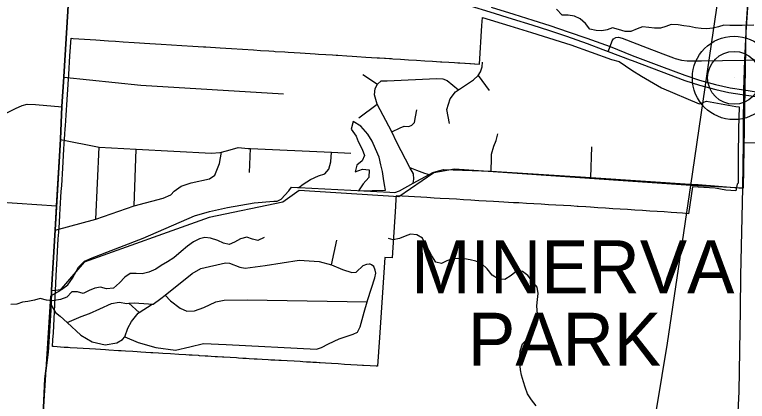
# Model space of a CAD drawing. Extents: x 0 to 34, y 0 to 22.
# Drawn here: x 26.126 to 27.434, y 4.179 to 4.869 of the extents above; entities that cross this region are included whole.
import ezdxf

# ---------------------------------------------------------------- set-up
doc = ezdxf.new("R2010")
doc.units = 0
for name, color, linetype in [('GM_X_City_Street', 7, 'Continuous'), ('GM_X_Corporation', 7, 'Continuous'), ('GM_X_Corporation_Text', 7, 'Continuous'), ('GM_X_County_Road', 7, 'Continuous'), ('GM_X_Minor_Lake', 7, 'Continuous'), ('GM_X_Minor_River', 7, 'Continuous'), ('GM_X_Rail_Line', 7, 'Continuous'), ('GM_X_State_Route', 7, 'Continuous'), ('GM_X_Unincorporated', 7, 'Continuous'), ('GM_X_Unincorporated_Location', 7, 'Continuous')]:
    doc.layers.add(name, color=color, linetype=linetype)

msp = doc.modelspace()

# ---------------------------------------------------------------- linework, layer by layer
at = {"layer": 'GM_X_City_Street'}
for p, q in [((26.7469, 4.7623), (26.7735, 4.745)), ((26.9529, 4.7602), (26.9729, 4.7335)), ((26.74, 4.6848), (26.7725, 4.7094)), ((26.2703, 4.5039), (26.2767, 4.6323)), ((27.1542, 4.5784), (27.1557, 4.6329)), ((26.3387, 4.528), (26.3427, 4.6289)), ((26.5447, 4.5871), (26.5467, 4.6302)), ((27.3456, 4.5656), (27.4257, 4.5596)), ((25.942, 4.5444), (26.2001, 4.5279)), ((26.6909, 4.4223), (26.7007, 4.4663)), ((26.3292, 4.3538), (26.3479, 4.3372))]:
    msp.add_line(p, q, dxfattribs=at)
for points in [[(26.9017, 4.6745), (26.8972, 4.6996), (26.9032, 4.7186), (26.9126, 4.7315), (26.9178, 4.7351), (26.9448, 4.7525), (26.9529, 4.7602), (26.957, 4.7669), (26.9601, 4.776), (26.9609, 4.7844)], [(26.2133, 4.7576), (26.3507, 4.7434), (26.6052, 4.7275)], [(26.7735, 4.745), (26.7796, 4.7507), (26.7903, 4.751), (26.8786, 4.7552), (26.8901, 4.7548), (26.8978, 4.7513), (26.9178, 4.7351)], [(26.8371, 4.5683), (26.838, 4.5753), (26.8377, 4.5852), (26.8309, 4.5963), (26.808, 4.6408), (26.7986, 4.6598), (26.7725, 4.7094), (26.768, 4.7257), (26.7692, 4.7371), (26.7735, 4.745)], [(25.8924, 4.6456), (25.9492, 4.6408), (25.9673, 4.6384), (25.9779, 4.639), (25.9875, 4.64), (25.9978, 4.6421), (26.0092, 4.6461), (26.0257, 4.653), (26.1046, 4.6905), (26.1269, 4.7014), (26.1389, 4.707), (26.1476, 4.7091), (26.1625, 4.7086), (26.2101, 4.7046)], [(26.7986, 4.6598), (26.8138, 4.6672), (26.821, 4.6698), (26.829, 4.6697), (26.8344, 4.672), (26.8393, 4.6765), (26.8413, 4.6864), (26.8437, 4.6993)], [(26.2073, 4.6464), (26.2767, 4.6323), (26.3427, 4.6289), (26.4771, 4.6221), (26.492, 4.6229), (26.4949, 4.6237), (26.5102, 4.6279), (26.5243, 4.6318), (26.5422, 4.6304), (26.5467, 4.6302), (26.6909, 4.6237), (26.7256, 4.6221)], [(26.9761, 4.5899), (26.9766, 4.6129), (26.9768, 4.6198), (26.9811, 4.6343), (26.9853, 4.6445), (26.988, 4.6563)], [(26.1981, 4.4844), (26.2703, 4.5039), (26.3387, 4.528), (26.3908, 4.5416), (26.4045, 4.5477), (26.4102, 4.5542), (26.4227, 4.563), (26.4409, 4.5688), (26.4732, 4.5758), (26.4827, 4.5823), (26.4913, 4.6036), (26.4949, 4.6237)], [(26.6331, 4.5607), (26.6403, 4.5667), (26.6539, 4.5747), (26.668, 4.5812), (26.6794, 4.5851), (26.6862, 4.5931), (26.6899, 4.6064), (26.6909, 4.6237)], [(26.1917, 4.3766), (26.209, 4.3786), (26.2206, 4.3865), (26.2289, 4.3985), (26.2393, 4.418), (26.2505, 4.4288), (26.264, 4.4351), (26.3552, 4.4702), (26.4468, 4.5098), (26.4736, 4.5175), (26.5057, 4.5246), (26.5531, 4.5332), (26.5885, 4.5361), (26.5942, 4.5359), (26.6016, 4.5399), (26.6149, 4.5548), (26.6196, 4.5611), (26.6303, 4.5608), (26.6331, 4.5607), (26.7951, 4.5519), (26.8042, 4.5516), (26.8123, 4.5548), (26.8371, 4.5683), (26.8653, 4.5835), (26.872, 4.5872), (26.882, 4.5904), (26.8911, 4.5924), (26.9761, 4.5899), (27.1542, 4.5784), (27.3406, 4.5659), (27.3456, 4.5656)], [(26.8309, 4.5963), (26.843, 4.5912), (26.8571, 4.5861), (26.8653, 4.5835)], [(26.1908, 4.3507), (26.1985, 4.3376), (26.2068, 4.3311), (26.2191, 4.3197), (26.2436, 4.297), (26.2641, 4.2847), (26.2873, 4.2799), (26.3082, 4.2832), (26.3182, 4.2889), (26.322, 4.2942), (26.3459, 4.2838), (26.3775, 4.2748), (26.4129, 4.27), (26.4384, 4.2759), (26.4628, 4.2819), (26.5032, 4.2804), (26.6642, 4.2718), (26.6733, 4.2748), (26.6856, 4.2815), (26.7046, 4.2905), (26.7298, 4.2987), (26.7378, 4.3021), (26.7421, 4.312), (26.7495, 4.3378), (26.7549, 4.3566), (26.7561, 4.3606), (26.7688, 4.3993), (26.7704, 4.4077), (26.7693, 4.413), (26.7667, 4.4195), (26.7625, 4.4225), (26.7591, 4.4241)], [(26.2191, 4.3197), (26.2445, 4.3301), (26.2594, 4.3353), (26.2777, 4.3439), (26.2987, 4.3537), (26.3121, 4.3559), (26.3258, 4.3535), (26.3292, 4.3538), (26.3391, 4.3546), (26.3646, 4.3529), (26.3712, 4.3525), (26.373, 4.3524), (26.3864, 4.3622), (26.394, 4.3683), (26.4422, 4.4068), (26.4579, 4.4162), (26.5017, 4.4262), (26.5093, 4.4253), (26.5276, 4.4184), (26.5371, 4.4164), (26.5729, 4.4215), (26.6335, 4.4306), (26.6689, 4.4285), (26.6909, 4.4223), (26.7111, 4.4141), (26.7274, 4.4087), (26.7354, 4.4094), (26.7477, 4.4215), (26.7541, 4.4237), (26.7591, 4.4241)], [(26.394, 4.3683), (26.4038, 4.3583), (26.4209, 4.3449), (26.4331, 4.3395), (26.4468, 4.3405), (26.4632, 4.3461), (26.4849, 4.3563), (26.4994, 4.3592), (26.5409, 4.3597), (26.7549, 4.3566)], [(26.322, 4.2942), (26.3274, 4.3094), (26.334, 4.3215), (26.3458, 4.3359), (26.3479, 4.3372), (26.3712, 4.3525)]]:
    msp.add_lwpolyline(points, dxfattribs=at)
at = {"layer": 'GM_X_Corporation'}
for points in [[(26.2923, 5.9946), (26.2834, 5.8568), (26.2709, 5.6764), (26.2638, 5.5626), (26.2598, 5.4936), (26.2368, 5.1439), (26.2339, 5.0948), (26.2333, 5.0856), (26.2296, 5.0221), (26.2131, 4.7582), (26.2099, 4.7051), (26.2071, 4.647), (26.1979, 4.4849), (26.1915, 4.3772), (26.1905, 4.3512), (26.1852, 4.2668), (26.1795, 4.2187), (26.176, 4.1418)], [(26.176, 4.1418), (26.1795, 4.2187), (26.1852, 4.2668), (26.1905, 4.3512), (26.1915, 4.3772), (26.1979, 4.4849), (26.2071, 4.647), (26.2099, 4.7051), (26.2131, 4.7582), (26.2296, 5.0221), (26.2333, 5.0856), (26.2339, 5.0948), (26.2368, 5.1439), (26.2598, 5.4936), (26.2638, 5.5626), (26.2709, 5.6764), (26.2834, 5.8568), (26.2923, 5.9946)]]:
    msp.add_lwpolyline(points, dxfattribs=at)
for points in [[(26.1931, 4.2765), (26.1938, 4.2888), (26.1946, 4.3013), (26.1953, 4.3135), (26.2002, 4.4147), (26.2006, 4.4222), (26.2021, 4.4466), (26.2028, 4.4578), (26.2035, 4.4691), (26.2043, 4.4806), (26.2053, 4.4978), (26.2062, 4.5118), (26.2068, 4.5222), (26.2075, 4.5326), (26.2082, 4.5432), (26.2088, 4.5536), (26.2095, 4.5641), (26.2101, 4.5743), (26.2108, 4.5847), (26.2115, 4.5952), (26.2122, 4.6065), (26.2129, 4.6178), (26.2136, 4.6291), (26.2142, 4.6387), (26.2152, 4.6555), (26.2159, 4.6655), (26.2162, 4.6708), (26.2174, 4.6895), (26.218, 4.6986), (26.2186, 4.7084), (26.2214, 4.7538), (26.222, 4.7625), (26.2242, 4.7954), (26.2263, 4.8269), (26.23, 4.8265), (26.2706, 4.8239), (26.2932, 4.8225), (26.3056, 4.8217), (26.3191, 4.8208), (26.3387, 4.8196), (26.367, 4.8178), (26.3869, 4.8166), (26.4055, 4.8154), (26.4241, 4.8142), (26.4437, 4.813), (26.4625, 4.8118), (26.4669, 4.8116), (26.4927, 4.8099), (26.5126, 4.8086), (26.5324, 4.8073), (26.5521, 4.8061), (26.5642, 4.8053), (26.5792, 4.8043), (26.5881, 4.8037), (26.5906, 4.8036), (26.6076, 4.8025), (26.614, 4.8021), (26.635, 4.8008), (26.6623, 4.7992), (26.6681, 4.7988), (26.6808, 4.798), (26.6928, 4.7973), (26.6994, 4.7969), (26.7023, 4.7967), (26.7185, 4.7956), (26.7278, 4.795), (26.7361, 4.7945), (26.7523, 4.7934), (26.7727, 4.7922), (26.7769, 4.7919), (26.7981, 4.7906), (26.8006, 4.7904), (26.8146, 4.7895), (26.8288, 4.7886), (26.8432, 4.7877), (26.8575, 4.7868), (26.8713, 4.7859), (26.8856, 4.785), (26.888, 4.7849), (26.9005, 4.7841), (26.9109, 4.7834), (26.9166, 4.7831), (26.9204, 4.7828), (26.9555, 4.7807), (26.9595, 4.85), (26.9606, 4.8642), (27.0094, 4.8491), (27.0485, 4.837), (27.0995, 4.8213), (27.1182, 4.8155), (27.1911, 4.7888), (27.205, 4.7852), (27.2273, 4.7697), (27.2446, 4.7594), (27.2803, 4.7384), (27.3477, 4.7098), (27.3608, 4.7148), (27.413, 4.7053), (27.4187, 4.7043), (27.4179, 4.6655), (27.4169, 4.6148), (27.417, 4.5898), (27.4172, 4.5682), (27.4156, 4.5666), (27.413, 4.5548), (27.3952, 4.5555), (27.3758, 4.5594), (27.3357, 4.5619), (27.3286, 4.5136), (27.3177, 4.5147), (27.3078, 4.5153), (27.2976, 4.516), (27.2851, 4.5168), (27.2727, 4.5176), (27.2593, 4.5184), (27.2464, 4.5193), (27.2329, 4.5201), (27.2197, 4.521), (27.2065, 4.5218), (27.1934, 4.5227), (27.1803, 4.5235), (27.1669, 4.5244), (27.1537, 4.5252), (27.1451, 4.5259), (27.1316, 4.5267), (27.1295, 4.5268), (27.1184, 4.5275), (27.1051, 4.5283), (27.0918, 4.529), (27.0785, 4.5298), (27.0653, 4.5306), (27.0522, 4.5314), (27.039, 4.5321), (27.0253, 4.5329), (27.016, 4.5334), (26.9897, 4.5349), (26.9805, 4.5355), (26.9672, 4.5362), (26.954, 4.537), (26.9401, 4.5378), (26.9271, 4.5386), (26.9143, 4.5394), (26.9012, 4.5401), (26.885, 4.5411), (26.8746, 4.5417), (26.8613, 4.5425), (26.8064, 4.5457), (26.8061, 4.5405), (26.8052, 4.5268), (26.7995, 4.4348), (26.7866, 4.4357), (26.7767, 4.293), (26.7731, 4.2413), (26.7712, 4.2414), (26.7599, 4.2421), (26.7485, 4.2428), (26.7465, 4.2429), (26.7372, 4.2435), (26.7258, 4.2442), (26.7145, 4.2448), (26.7031, 4.2455), (26.691, 4.2463), (26.6804, 4.2469), (26.6712, 4.2475), (26.6691, 4.2476), (26.6641, 4.2479), (26.6578, 4.2483), (26.6538, 4.2485), (26.6464, 4.2489), (26.6397, 4.2493), (26.6351, 4.2496), (26.6246, 4.2502), (26.6118, 4.2509), (26.6012, 4.2515), (26.5972, 4.2517), (26.5898, 4.2521), (26.5828, 4.2525), (26.5784, 4.2528), (26.5671, 4.2534), (26.5582, 4.2539), (26.5557, 4.2541), (26.5534, 4.2542), (26.5443, 4.2547), (26.5386, 4.2551), (26.533, 4.2555), (26.5253, 4.2559), (26.5216, 4.2562), (26.51, 4.2569), (26.4989, 4.2576), (26.4968, 4.2577), (26.4876, 4.2583), (26.4835, 4.2585), (26.4762, 4.259), (26.4704, 4.2593), (26.4654, 4.2596), (26.4556, 4.2602), (26.4536, 4.2604), (26.4422, 4.2611), (26.4372, 4.2614), (26.4309, 4.2618), (26.4189, 4.2625), (26.4035, 4.2634), (26.3899, 4.2643), (26.3821, 4.2648), (26.3725, 4.2654), (26.3689, 4.2656), (26.3506, 4.2667), (26.3442, 4.2671), (26.3364, 4.2676), (26.3233, 4.2684), (26.3158, 4.2689), (26.3109, 4.2692), (26.2935, 4.2702), (26.2875, 4.2706), (26.2699, 4.2717), (26.2592, 4.2724), (26.2478, 4.273), (26.237, 4.2737), (26.2247, 4.2745), (26.2212, 4.2746), (26.2138, 4.2751), (26.195, 4.2764)], [(26.9606, 4.8642), (27.0094, 4.8491), (27.0485, 4.837), (27.0995, 4.8213), (27.1182, 4.8155), (27.1911, 4.7888), (27.205, 4.7852), (27.2273, 4.7697), (27.2446, 4.7594), (27.2803, 4.7384), (27.3477, 4.7098), (27.3608, 4.7148), (27.413, 4.7053), (27.4187, 4.7043), (27.4179, 4.6655), (27.4169, 4.6148), (27.417, 4.5898), (27.4172, 4.5682), (27.4156, 4.5666), (27.413, 4.5548), (27.3952, 4.5555), (27.3758, 4.5594), (27.3357, 4.5619), (27.3286, 4.5136), (27.3177, 4.5147), (27.3078, 4.5153), (27.2976, 4.516), (27.2851, 4.5168), (27.2727, 4.5176), (27.2593, 4.5184), (27.2464, 4.5193), (27.2329, 4.5201), (27.2197, 4.521), (27.2065, 4.5218), (27.1934, 4.5227), (27.1803, 4.5235), (27.1669, 4.5244), (27.1537, 4.5252), (27.1451, 4.5259), (27.1316, 4.5267), (27.1295, 4.5268), (27.1184, 4.5275), (27.1051, 4.5283), (27.0918, 4.529), (27.0785, 4.5298), (27.0653, 4.5306), (27.0522, 4.5314), (27.039, 4.5321), (27.0253, 4.5329), (27.016, 4.5334), (26.9897, 4.5349), (26.9805, 4.5355), (26.9672, 4.5362), (26.954, 4.537), (26.9401, 4.5378), (26.9271, 4.5386), (26.9143, 4.5394), (26.9012, 4.5401), (26.885, 4.5411), (26.8746, 4.5417), (26.8613, 4.5425), (26.8064, 4.5457), (26.8061, 4.5405), (26.8052, 4.5268), (26.7995, 4.4348), (26.7866, 4.4357), (26.7767, 4.293), (26.7731, 4.2413), (26.7712, 4.2414), (26.7599, 4.2421), (26.7485, 4.2428), (26.7465, 4.2429), (26.7372, 4.2435), (26.7258, 4.2442), (26.7145, 4.2448), (26.7031, 4.2455), (26.691, 4.2463), (26.6804, 4.2469), (26.6712, 4.2475), (26.6691, 4.2476), (26.6641, 4.2479), (26.6578, 4.2483), (26.6538, 4.2485), (26.6464, 4.2489), (26.6397, 4.2493), (26.6351, 4.2496), (26.6246, 4.2502), (26.6118, 4.2509), (26.6012, 4.2515), (26.5972, 4.2517), (26.5898, 4.2521), (26.5828, 4.2525), (26.5784, 4.2528), (26.5671, 4.2534), (26.5582, 4.2539), (26.5557, 4.2541), (26.5534, 4.2542), (26.5443, 4.2547), (26.5386, 4.2551), (26.533, 4.2555), (26.5253, 4.2559), (26.5216, 4.2562), (26.51, 4.2569), (26.4989, 4.2576), (26.4968, 4.2577), (26.4876, 4.2583), (26.4835, 4.2585), (26.4762, 4.259), (26.4704, 4.2593), (26.4654, 4.2596), (26.4556, 4.2602), (26.4536, 4.2604), (26.4422, 4.2611), (26.4372, 4.2614), (26.4309, 4.2618), (26.4189, 4.2625), (26.4035, 4.2634), (26.3899, 4.2643), (26.3821, 4.2648), (26.3725, 4.2654), (26.3689, 4.2656), (26.3506, 4.2667), (26.3442, 4.2671), (26.3364, 4.2676), (26.3233, 4.2684), (26.3158, 4.2689), (26.3109, 4.2692), (26.2935, 4.2702), (26.2875, 4.2706), (26.2699, 4.2717), (26.2592, 4.2724), (26.2478, 4.273), (26.237, 4.2737), (26.2247, 4.2745), (26.2212, 4.2746), (26.2138, 4.2751), (26.195, 4.2764), (26.1931, 4.2765), (26.1938, 4.2888), (26.1946, 4.3013), (26.1953, 4.3135), (26.2002, 4.4147), (26.2006, 4.4222), (26.2021, 4.4466), (26.2028, 4.4578), (26.2035, 4.4691), (26.2043, 4.4806), (26.2053, 4.4978), (26.2062, 4.5118), (26.2068, 4.5222), (26.2075, 4.5326), (26.2082, 4.5432), (26.2088, 4.5536), (26.2095, 4.5641), (26.2101, 4.5743), (26.2108, 4.5847), (26.2115, 4.5952), (26.2122, 4.6065), (26.2129, 4.6178), (26.2136, 4.6291), (26.2142, 4.6387), (26.2152, 4.6555), (26.2159, 4.6655), (26.2162, 4.6708), (26.2174, 4.6895), (26.218, 4.6986), (26.2186, 4.7084), (26.2214, 4.7538), (26.222, 4.7625), (26.2242, 4.7954), (26.2263, 4.8269), (26.23, 4.8265), (26.2706, 4.8239), (26.2932, 4.8225), (26.3056, 4.8217), (26.3191, 4.8208), (26.3387, 4.8196), (26.367, 4.8178), (26.3869, 4.8166), (26.4055, 4.8154), (26.4241, 4.8142), (26.4437, 4.813), (26.4625, 4.8118), (26.4669, 4.8116), (26.4927, 4.8099), (26.5126, 4.8086), (26.5324, 4.8073), (26.5521, 4.8061), (26.5642, 4.8053), (26.5792, 4.8043), (26.5881, 4.8037), (26.5906, 4.8036), (26.6076, 4.8025), (26.614, 4.8021), (26.635, 4.8008), (26.6623, 4.7992), (26.6681, 4.7988), (26.6808, 4.798), (26.6928, 4.7973), (26.6994, 4.7969), (26.7023, 4.7967), (26.7185, 4.7956), (26.7278, 4.795), (26.7361, 4.7945), (26.7523, 4.7934), (26.7727, 4.7922), (26.7769, 4.7919), (26.7948, 4.7908), (26.8006, 4.7904), (26.8146, 4.7895), (26.8288, 4.7886), (26.8432, 4.7877), (26.8575, 4.7868), (26.8713, 4.7859), (26.8856, 4.785), (26.888, 4.7849), (26.9005, 4.7841), (26.9109, 4.7834), (26.9166, 4.7831), (26.9204, 4.7828), (26.9396, 4.7816), (26.9555, 4.7807), (26.9595, 4.85)]]:
    msp.add_lwpolyline(points, close=True, dxfattribs=at)
at = {"layer": 'GM_X_County_Road'}
msp.add_line((27.4269, 4.6411), (27.5849, 4.6383), dxfattribs=at)
for points in [[(26.1762, 4.1412), (26.1797, 4.2182), (26.1854, 4.2662), (26.1908, 4.3507), (26.1917, 4.3766), (26.1981, 4.4844), (26.2001, 4.5279), (26.2073, 4.6464), (26.2101, 4.7046), (26.2133, 4.7576), (26.2298, 5.0215), (26.2336, 5.0851)], [(27.1849, 4.8034), (27.1884, 4.812), (27.1925, 4.8222), (27.1948, 4.8257), (27.199, 4.8282), (27.2035, 4.8287), (27.2102, 4.827), (27.2178, 4.8242), (27.2469, 4.8131), (27.2828, 4.7991), (27.3018, 4.7922)], [(27.3018, 4.7922), (27.3048, 4.7911), (27.316, 4.7881), (27.3259, 4.7867), (27.3517, 4.7867), (27.3894, 4.7873), (27.4288, 4.7879), (27.4717, 4.7895)]]:
    msp.add_lwpolyline(points, dxfattribs=at)
at = {"layer": 'GM_X_Minor_Lake'}
for points in [[(26.7878, 4.5559), (26.7856, 4.5654), (26.7838, 4.5768), (26.7821, 4.5893), (26.7795, 4.6011), (26.7762, 4.6144), (26.7696, 4.6297), (26.7636, 4.6434), (26.7558, 4.656), (26.7434, 4.6698), (26.7298, 4.6783), (26.7263, 4.6647), (26.7352, 4.6524), (26.7389, 4.6429), (26.746, 4.6292), (26.7501, 4.6177), (26.7462, 4.6079), (26.7366, 4.6004), (26.7335, 4.5883), (26.7464, 4.5935), (26.7582, 4.5918), (26.7577, 4.5782), (26.7477, 4.5669), (26.7396, 4.5548)], [(26.7396, 4.5548), (26.7878, 4.5559)]]:
    msp.add_lwpolyline(points, dxfattribs=at)
at = {"layer": 'GM_X_Minor_River'}
for points in [[(27.4449, 4.8503), (27.4244, 4.8498), (27.4134, 4.8495), (27.4024, 4.8496), (27.3918, 4.8501), (27.3823, 4.8471), (27.3717, 4.845), (27.361, 4.8439), (27.3508, 4.8444), (27.341, 4.8456), (27.3304, 4.848), (27.3202, 4.8492), (27.3099, 4.8509), (27.2978, 4.8514), (27.2883, 4.848), (27.2784, 4.8447), (27.2678, 4.8448), (27.2576, 4.8464), (27.2466, 4.8473), (27.2371, 4.844), (27.2257, 4.8388), (27.2155, 4.8388), (27.2034, 4.8424), (27.1928, 4.8455), (27.1833, 4.8418), (27.1738, 4.8404), (27.1639, 4.8409), (27.1526, 4.8432), (27.1447, 4.8536), (27.135, 4.8616), (27.1251, 4.8663), (27.1138, 4.8679), (27.1028, 4.8684), (27.0927, 4.8788)], [(26.9389, 4.4313), (26.9287, 4.4333), (26.9169, 4.4338), (26.9067, 4.4328), (26.8968, 4.4298), (26.8873, 4.425), (26.8775, 4.4274), (26.87, 4.4384), (26.8648, 4.4484), (26.8581, 4.4594), (26.8536, 4.4701), (26.8438, 4.4763), (26.8321, 4.4775), (26.8226, 4.4734), (26.8123, 4.4694), (26.8013, 4.4672), (26.793, 4.4692)], [(26.5709, 4.4713), (26.5599, 4.4661), (26.55, 4.4681), (26.5398, 4.4716), (26.5288, 4.4686), (26.5181, 4.4631), (26.5086, 4.459), (26.4984, 4.461), (26.4882, 4.466), (26.475, 4.4699), (26.4648, 4.4712), (26.4553, 4.4686), (26.445, 4.4637), (26.4339, 4.4559), (26.4225, 4.4465), (26.4099, 4.4352), (26.3984, 4.4277), (26.387, 4.421), (26.3775, 4.4146), (26.3649, 4.4094), (26.3531, 4.4065), (26.3425, 4.407), (26.3319, 4.4067), (26.322, 4.4004), (26.3128, 4.3902), (26.3021, 4.3808), (26.2896, 4.3798), (26.279, 4.3825), (26.2688, 4.3807), (26.2585, 4.3766), (26.2478, 4.3711), (26.2376, 4.3742), (26.2278, 4.3743), (26.2186, 4.3645), (26.2072, 4.3604), (26.1928, 4.3583), (26.1825, 4.3595), (26.1712, 4.3623), (26.1609, 4.3593), (26.1492, 4.3572), (26.1393, 4.3561), (26.1294, 4.352), (26.1188, 4.3518)], [(27.0567, 4.1708), (27.048, 4.1815), (27.0409, 4.1922), (27.0369, 4.204), (27.0339, 4.2136), (27.0303, 4.2254), (27.0284, 4.2349), (27.0274, 4.2478), (27.0271, 4.2573), (27.028, 4.2683), (27.0319, 4.2812), (27.0422, 4.2921), (27.0514, 4.3034), (27.0564, 4.3136), (27.06, 4.3246), (27.0589, 4.3341), (27.0579, 4.3493), (27.0588, 4.3607), (27.0604, 4.3713), (27.0582, 4.3827), (27.0503, 4.3923), (27.0417, 4.4034), (27.0319, 4.4103), (27.0217, 4.4112), (27.0118, 4.4033), (27.0004, 4.3962), (26.9894, 4.3967), (26.9781, 4.404), (26.9691, 4.4155), (26.9589, 4.4251), (26.9491, 4.4289), (26.9389, 4.4313)]]:
    msp.add_lwpolyline(points, dxfattribs=at)
at = {"layer": 'GM_X_Rail_Line'}
for points in [[(26.5612, 3.3841), (26.5629, 3.3871), (26.6048, 3.434), (26.658, 3.4848), (27.0231, 3.755), (27.1106, 3.8337), (27.1525, 3.887), (27.1994, 3.9542), (27.2298, 4.0138), (27.259, 4.0938), (27.2717, 4.1673), (27.2907, 4.2828), (27.3324, 4.5642), (27.3731, 4.841), (27.4618, 5.4436), (27.4644, 5.4727), (27.4529, 6.0004), (27.4552, 6.6706), (27.4619, 6.8197), (27.4824, 7.181), (27.4896, 7.3031), (27.5213, 7.8422), (27.5447, 8.1693), (27.5992, 8.3999)], [(27.4824, 7.181), (27.6143, 6.7182), (27.6266, 6.646), (27.6291, 6.4258), (27.6038, 5.9295), (27.5895, 5.5554), (27.5368, 5.337), (27.4888, 5.1639), (27.437, 4.9331), (27.4309, 4.8441), (27.4259, 4.5594), (27.3324, 4.5642)], [(27.3324, 4.5642), (26.9109, 4.5934), (26.8739, 4.5866), (26.8112, 4.5441), (26.6332, 4.5554), (26.6045, 4.5345), (26.4726, 4.5067), (26.2499, 4.4271), (26.2048, 4.3755), (26.1896, 4.3663), (26.1268, 3.3841)]]:
    msp.add_lwpolyline(points, dxfattribs=at)
at = {"layer": 'GM_X_State_Route'}
msp.add_line((27.4257, 4.5596), (27.4269, 4.6411), dxfattribs=at)
for points in [[(27.4288, 4.7879), (27.4313, 4.8376), (27.4363, 4.9087), (27.4436, 4.9566), (27.4572, 5.0284), (27.4826, 5.1262), (27.5166, 5.2529)], [(26.3298, 5.0601), (26.3394, 5.0576), (26.3927, 5.0437), (26.4452, 5.0299), (26.5057, 5.014), (26.5311, 5.0075), (26.5727, 4.9964), (26.6036, 4.9879), (26.6625, 4.9703), (26.7297, 4.9494), (26.7905, 4.9307), (26.8486, 4.9127), (26.8505, 4.9121), (26.8968, 4.8978), (26.9094, 4.894), (26.939, 4.8848), (26.9736, 4.874), (27.0134, 4.8617), (27.0487, 4.851), (27.0806, 4.8407), (27.1104, 4.8308), (27.1473, 4.8177), (27.1755, 4.807)], [(26.9763, 4.8824), (27.0168, 4.8698), (27.0507, 4.8593), (27.0808, 4.8497), (27.1136, 4.8387), (27.1471, 4.827), (27.1884, 4.812)], [(27.1755, 4.807), (27.1849, 4.8034), (27.2242, 4.7886)], [(27.1884, 4.812), (27.2281, 4.7964), (27.2804, 4.7765), (27.322, 4.7609), (27.3479, 4.7523), (27.3766, 4.7444), (27.4029, 4.7386), (27.4274, 4.7347), (27.4535, 4.731)], [(27.2242, 4.7886), (27.2281, 4.7871), (27.2795, 4.7676), (27.3222, 4.7517), (27.3483, 4.7432), (27.3771, 4.7352), (27.4007, 4.7302), (27.4241, 4.7265)], [(27.4271, 4.7192), (27.4272, 4.726), (27.4274, 4.7347), (27.4288, 4.7879)], [(27.4241, 4.7265), (27.4272, 4.726), (27.4539, 4.7223), (27.4837, 4.7208), (27.5151, 4.7206), (27.5395, 4.7218), (27.5537, 4.7229), (27.5673, 4.7239), (27.578, 4.7253), (27.5975, 4.7284), (27.6278, 4.7344), (27.6607, 4.743), (27.6837, 4.7498), (27.7083, 4.7571)], [(27.4269, 4.6411), (27.4269, 4.6807), (27.4271, 4.7192)], [(27.4211, 4.3422), (27.422, 4.4034), (27.4257, 4.5596)], [(27.3652, 4.008), (27.3884, 4.0495), (27.4065, 4.0866), (27.412, 4.112), (27.4158, 4.1352), (27.4189, 4.1962), (27.4211, 4.3422)]]:
    msp.add_lwpolyline(points, dxfattribs=at)
at = {"layer": 'GM_X_Unincorporated'}
for radius in [0.0744, 0.0472]:
    msp.add_circle((27.4098, 4.7562), radius, dxfattribs=at)
at = {"layer": 'GM_X_Unincorporated_Location'}
msp.add_line((27.4098, 4.7562), (27.4098, 4.7562), dxfattribs=at)

# ---------------------------------------------------------------- texts
at = {"layer": 'GM_X_Corporation_Text'}
for s, p in [('MINERVA', (26.8335, 4.3715)), ('PARK', (26.9348, 4.2422))]:
    msp.add_text(s, height=0.0947, rotation=0, dxfattribs=at).set_placement(p)

doc.saveas('drawing.dxf')
